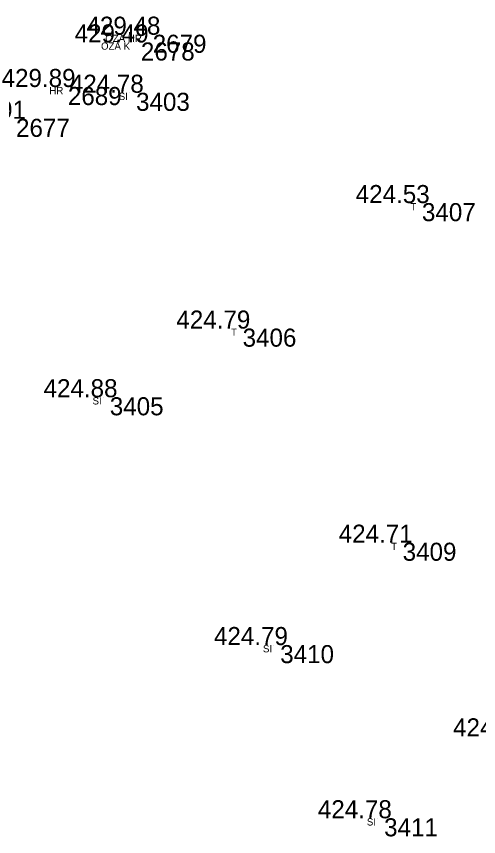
# Model space of a CAD drawing. Extents: x -639390 to -639075, y -1138747 to -1138358.
# Drawn here: x -639319.41 to -639300.23, y -1138436.19 to -1138402.14 of the extents above; entities that cross this region are included whole.
import ezdxf

# ---------------------------------------------------------------- set-up
doc = ezdxf.new("R2010")
doc.units = 0
for name, color, linetype in [('Vrstva 11', 7, 'Continuous'), ('Vrstva 12', 7, 'Continuous'), ('Vrstva 13', 7, 'Continuous'), ('Vrstva 57', 7, 'Continuous')]:
    doc.layers.add(name, color=color, linetype=linetype)

msp = doc.modelspace()

# ---------------------------------------------------------------- linework, layer by layer
at = {"layer": 'Vrstva 11'}
for p, q in [((-639314.03, -1138402.9), (-639314.03, -1138402.9)), ((-639314.52, -1138403.22), (-639314.52, -1138403.22)), ((-639317.55, -1138405.07), (-639317.55, -1138405.07)), ((-639314.72, -1138405.31), (-639314.72, -1138405.31)), ((-639302.86, -1138409.89), (-639302.86, -1138409.89)), ((-639310.3, -1138415.1), (-639310.3, -1138415.1)), ((-639315.81, -1138417.95), (-639315.81, -1138417.95)), ((-639303.66, -1138423.99), (-639303.66, -1138423.99)), ((-639308.74, -1138428.24), (-639308.74, -1138428.24)), ((-639304.43, -1138435.43), (-639304.43, -1138435.43))]:
    msp.add_line(p, q, dxfattribs=at)

# ---------------------------------------------------------------- texts
at = {"layer": 'Vrstva 12'}
for s, p in [('429.48 ', (-639316.499, -1138402.9)), ('429.49 ', (-639316.989, -1138403.22)), ('429.89 ', (-639320.019, -1138405.07)), ('424.78 ', (-639317.189, -1138405.31)), ('429.91 ', (-639322.075, -1138406.39)), ('424.53 ', (-639305.329, -1138409.89)), ('424.79 ', (-639312.769, -1138415.1)), ('424.88 ', (-639318.279, -1138417.95)), ('424.71 ', (-639306.035, -1138423.99)), ('424.79 ', (-639311.209, -1138428.24)), ('424.65 ', (-639301.29, -1138432.03)), ('424.78 ', (-639306.899, -1138435.43))]:
    msp.add_text(s, height=0.75, dxfattribs=at).set_placement(p)
at = {"layer": 'Vrstva 13'}
for s, p in [(' 2678', (-639314.52, -1138403.97)), (' 2679', (-639314.03, -1138403.65)), (' 2689', (-639317.55, -1138405.82)), (' 3403', (-639314.72, -1138406.06)), (' 2677', (-639319.7, -1138407.14)), (' 3407', (-639302.86, -1138410.64)), (' 3406', (-639310.3, -1138415.85)), (' 3405', (-639315.81, -1138418.7)), (' 3409', (-639303.66, -1138424.74)), (' 3410', (-639308.74, -1138428.99)), (' 3411', (-639304.43, -1138436.18))]:
    msp.add_text(s, height=0.75, dxfattribs=at).set_placement(p)
at = {"layer": 'Vrstva 57'}
for s, p in [('OZA HR', (-639315.719, -1138403.2)), ('OZA K', (-639315.895, -1138403.52)), ('HR', (-639318.039, -1138405.37)), ('SI', (-639315.158, -1138405.61)), ('T', (-639303.06, -1138410.19)), ('T', (-639310.5, -1138415.4)), ('SI', (-639316.248, -1138418.25)), ('T', (-639303.86, -1138424.29)), ('SI', (-639309.178, -1138428.54)), ('SI', (-639304.868, -1138435.73))]:
    msp.add_text(s, height=0.3, dxfattribs=at).set_placement(p)

doc.saveas('drawing.dxf')
